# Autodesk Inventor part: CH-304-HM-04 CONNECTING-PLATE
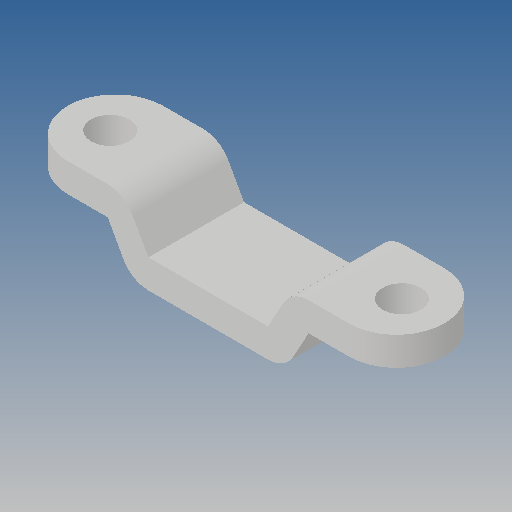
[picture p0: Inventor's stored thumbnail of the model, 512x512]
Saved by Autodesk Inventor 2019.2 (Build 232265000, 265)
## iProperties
Created: 2015-08
Part Number: CH-304-HM-04 CONNECTING-PLATE
Material: Ogólny
Document SubType Name: Modeling
Designer: CADENGINEERING4
Density: 1 g/cm^3
Appearance: Domyślna
Author: CADENGINEERING4
Revision Number: ÈÎºÎ
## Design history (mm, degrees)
feature "ÇÐ³ý-À­Éì1"
node "Bryła1"
